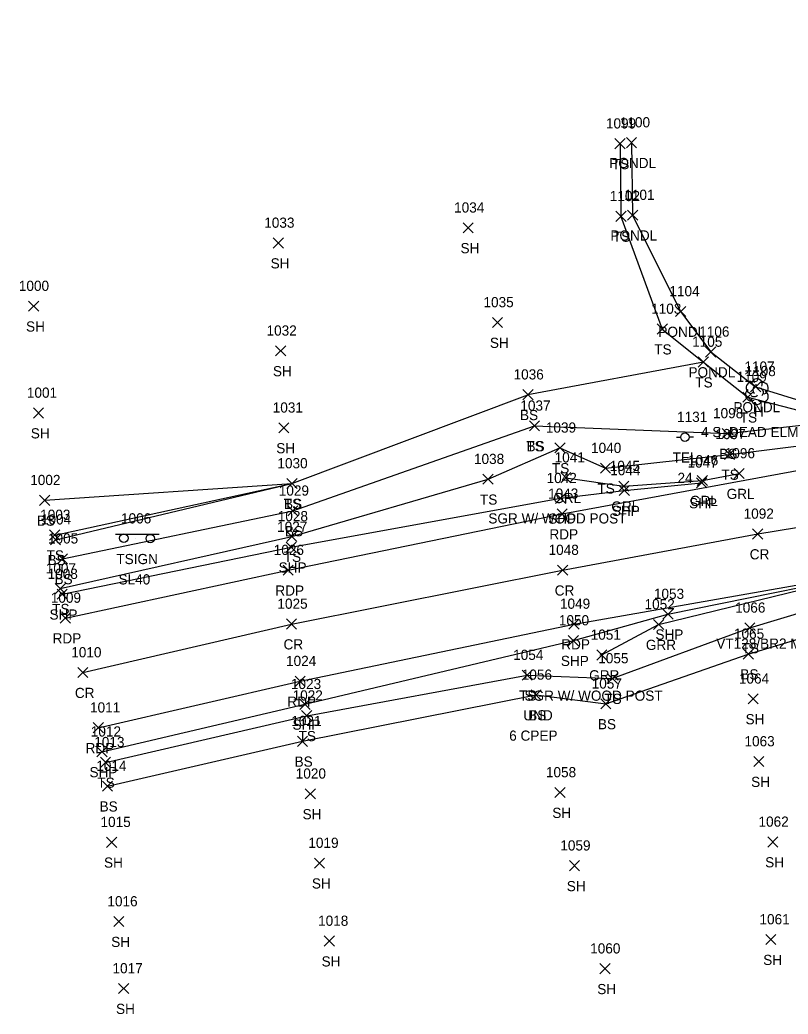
# Model space of a CAD drawing. Extents: x 1497084 to 1499861, y 734741 to 735567.
# Drawn here: x 1498155.1 to 1498306.3, y 735206.8 to 735402.3 of the extents above; entities that cross this region are included whole.
import ezdxf

# ---------------------------------------------------------------- set-up
doc = ezdxf.new("R2010")
doc.units = 0
for name, color, linetype in [('D_A', 7, 'Continuous'), ('D_C', 7, 'Continuous'), ('D_I', 7, 'Continuous'), ('D_TIC', 7, 'Continuous'), ('L_A', 7, 'Continuous'), ('L_C', 7, 'Continuous'), ('L_I', 7, 'Continuous'), ('L_TIC', 7, 'Continuous'), ('LAWE', 7, 'Continuous'), ('LELB', 7, 'Continuous'), ('LTD', 7, 'Continuous'), ('P_A', 7, 'Continuous'), ('P_I', 7, 'Continuous'), ('P_TIC', 7, 'Continuous'), ('PET', 7, 'Continuous'), ('PRC', 7, 'Continuous'), ('PSP', 7, 'Continuous'), ('R_A', 7, 'Continuous'), ('R_C', 7, 'Continuous'), ('R_I', 7, 'Continuous'), ('R_TIC', 7, 'Continuous'), ('RGR', 7, 'Continuous'), ('S_A', 7, 'Continuous'), ('S_C', 7, 'Continuous'), ('S_I', 7, 'Continuous'), ('SSGN', 7, 'Continuous'), ('U_A', 7, 'Continuous'), ('U_C', 7, 'Continuous'), ('U_I', 7, 'Continuous'), ('UP', 7, 'Continuous')]:
    doc.layers.add(name, color=color, linetype=linetype)

msp = doc.modelspace()

# ---------------------------------------------------------------- linework, layer by layer
at = {"layer": 'D_TIC'}
for points in [[(1498255.69, 735268.55), (1498257.69, 735270.55)], [(1498257.69, 735268.55), (1498255.69, 735270.55)]]:
    msp.add_lwpolyline(points, dxfattribs=at)
at = {"layer": 'L_TIC'}
for points in [[(1498272.21, 735376.95), (1498274.21, 735378.95)], [(1498274.21, 735376.95), (1498272.21, 735378.95)], [(1498274.46, 735377.17), (1498276.46, 735379.17)], [(1498276.46, 735377.17), (1498274.46, 735379.17)], [(1498272.39, 735362.67), (1498274.39, 735364.67)], [(1498274.39, 735362.67), (1498272.39, 735364.67)], [(1498274.69, 735362.91), (1498276.69, 735364.91)], [(1498276.69, 735362.91), (1498274.69, 735364.91)], [(1498242.32, 735360.42), (1498244.32, 735362.42)], [(1498244.32, 735360.42), (1498242.32, 735362.42)], [(1498204.95, 735357.43), (1498206.95, 735359.43)], [(1498206.95, 735357.43), (1498204.95, 735359.43)], [(1498156.81, 735345.01), (1498158.81, 735347.01)], [(1498158.81, 735345.01), (1498156.81, 735347.01)], [(1498284.13, 735343.96), (1498286.13, 735345.96)], [(1498286.13, 735343.96), (1498284.13, 735345.96)], [(1498248.1, 735341.8), (1498250.1, 735343.8)], [(1498250.1, 735341.8), (1498248.1, 735343.8)], [(1498280.53, 735340.51), (1498282.53, 735342.51)], [(1498282.53, 735340.51), (1498280.53, 735342.51)], [(1498205.4, 735336.22), (1498207.4, 735338.22)], [(1498207.4, 735336.22), (1498205.4, 735338.22)], [(1498290.05, 735336.01), (1498292.05, 735338.01)], [(1498292.05, 735336.01), (1498290.05, 735338.01)], [(1498288.61, 735334.02), (1498290.61, 735336.02)], [(1498290.61, 735334.02), (1498288.61, 735336.02)], [(1498298.89, 735329.14), (1498300.89, 735331.14)], [(1498300.89, 735329.14), (1498298.89, 735331.14)], [(1498254.08, 735327.59), (1498256.08, 735329.59)], [(1498256.08, 735327.59), (1498254.08, 735329.59)], [(1498297.36, 735327.12), (1498299.36, 735329.12)], [(1498299.36, 735327.12), (1498297.36, 735329.12)], [(1498157.74, 735324), (1498159.74, 735326)], [(1498159.74, 735324), (1498157.74, 735326)], [(1498206.05, 735321.08), (1498208.05, 735323.08)], [(1498208.05, 735321.08), (1498206.05, 735323.08)], [(1498255.36, 735321.46), (1498257.36, 735323.46)], [(1498257.36, 735321.46), (1498255.36, 735323.46)], [(1498255.36, 735321.46), (1498257.36, 735323.46)], [(1498257.36, 735321.46), (1498255.36, 735323.46)], [(1498293.28, 735319.97), (1498295.28, 735321.97)], [(1498295.28, 735319.97), (1498293.28, 735321.97)], [(1498260.39, 735317.14), (1498262.39, 735319.14)], [(1498262.39, 735317.14), (1498260.39, 735319.14)], [(1498293.75, 735315.86), (1498295.75, 735317.86)], [(1498295.75, 735315.86), (1498293.75, 735317.86)], [(1498269.35, 735313.14), (1498271.35, 735315.14)], [(1498271.35, 735313.14), (1498269.35, 735315.14)], [(1498207.63, 735310.12), (1498209.63, 735312.12)], [(1498209.63, 735310.12), (1498207.63, 735312.12)], [(1498207.63, 735310.12), (1498209.63, 735312.12)], [(1498209.63, 735310.12), (1498207.63, 735312.12)], [(1498207.63, 735310.12), (1498209.63, 735312.12)], [(1498209.63, 735310.12), (1498207.63, 735312.12)], [(1498246.23, 735310.97), (1498248.23, 735312.97)], [(1498248.23, 735310.97), (1498246.23, 735312.97)], [(1498158.97, 735306.83), (1498160.97, 735308.83)], [(1498160.97, 735306.83), (1498158.97, 735308.83)], [(1498207.82, 735304.75), (1498209.82, 735306.75)], [(1498209.82, 735304.75), (1498207.82, 735306.75)], [(1498160.93, 735299.99), (1498162.93, 735301.99)], [(1498162.93, 735299.99), (1498160.93, 735301.99)], [(1498207.61, 735299.72), (1498209.61, 735301.72)], [(1498209.61, 735299.72), (1498207.61, 735301.72)], [(1498161.08, 735299.08), (1498163.08, 735301.08)], [(1498163.08, 735299.08), (1498161.08, 735301.08)], [(1498162.46, 735295.33), (1498164.46, 735297.33)], [(1498164.46, 735295.33), (1498162.46, 735297.33)], [(1498162.03, 735289.46), (1498164.03, 735291.46)], [(1498164.03, 735289.46), (1498162.03, 735291.46)], [(1498297.74, 735281.74), (1498299.74, 735283.74)], [(1498299.74, 735281.74), (1498297.74, 735283.74)], [(1498297.45, 735276.6), (1498299.45, 735278.6)], [(1498299.45, 735276.6), (1498297.45, 735278.6)], [(1498253.94, 735272.44), (1498255.94, 735274.44)], [(1498255.94, 735272.44), (1498253.94, 735274.44)], [(1498270.69, 735271.78), (1498272.69, 735273.78)], [(1498272.69, 735271.78), (1498270.69, 735273.78)], [(1498255.69, 735268.55), (1498257.69, 735270.55)], [(1498257.69, 735268.55), (1498255.69, 735270.55)], [(1498269.41, 735266.8), (1498271.41, 735268.8)], [(1498271.41, 735266.8), (1498269.41, 735268.8)], [(1498298.42, 735267.78), (1498300.42, 735269.78)], [(1498300.42, 735267.78), (1498298.42, 735269.78)], [(1498210.53, 735264.46), (1498212.53, 735266.46)], [(1498212.53, 735264.46), (1498210.53, 735266.46)], [(1498209.71, 735259.44), (1498211.71, 735261.44)], [(1498211.71, 735259.44), (1498209.71, 735261.44)], [(1498170.92, 735255.29), (1498172.92, 735257.29)], [(1498172.92, 735255.29), (1498170.92, 735257.29)], [(1498299.52, 735255.45), (1498301.52, 735257.45)], [(1498301.52, 735255.45), (1498299.52, 735257.45)], [(1498171.32, 735250.62), (1498173.32, 735252.62)], [(1498173.32, 735250.62), (1498171.32, 735252.62)], [(1498211.24, 735249.1), (1498213.24, 735251.1)], [(1498213.24, 735249.1), (1498211.24, 735251.1)], [(1498260.4, 735249.36), (1498262.4, 735251.36)], [(1498262.4, 735249.36), (1498260.4, 735251.36)], [(1498172.15, 735239.58), (1498174.15, 735241.58)], [(1498174.15, 735239.58), (1498172.15, 735241.58)], [(1498302.28, 735239.64), (1498304.28, 735241.64)], [(1498304.28, 735239.64), (1498302.28, 735241.64)], [(1498213.07, 735235.48), (1498215.07, 735237.48)], [(1498215.07, 735235.48), (1498213.07, 735237.48)], [(1498263.23, 735234.96), (1498265.23, 735236.96)], [(1498265.23, 735234.96), (1498263.23, 735236.96)], [(1498173.57, 735223.98), (1498175.57, 735225.98)], [(1498175.57, 735223.98), (1498173.57, 735225.98)], [(1498214.98, 735220.15), (1498216.98, 735222.15)], [(1498216.98, 735220.15), (1498214.98, 735222.15)], [(1498301.9, 735220.44), (1498303.9, 735222.44)], [(1498303.9, 735220.44), (1498301.9, 735222.44)], [(1498269.24, 735214.71), (1498271.24, 735216.71)], [(1498271.24, 735214.71), (1498269.24, 735216.71)], [(1498174.52, 735210.81), (1498176.52, 735212.81)], [(1498176.52, 735210.81), (1498174.52, 735212.81)]]:
    msp.add_lwpolyline(points, dxfattribs=at)
at = {"layer": 'LAWE'}
msp.add_lwpolyline([(1498275.46, 735378.17), (1498275.69, 735363.91), (1498285.13, 735344.96), (1498291.05, 735337.01), (1498299.89, 735330.14), (1498310.47, 735326.85), (1498319.02, 735327.27), (1498323.8, 735327.85), (1498325.54, 735326.28), (1498335.98, 735328.26), (1498338.67, 735333.84), (1498347.71, 735340.62), (1498357.75, 735341.88), (1498365.93, 735349.29), (1498368.84, 735359.24), (1498365.54, 735374.35), (1498361.93, 735386.41), (1498357.1, 735395.06), (1498356, 735402.31)], dxfattribs=at)
at = {"layer": 'LELB'}
for points in [[(1498273.21, 735377.95), (1498273.39, 735363.67), (1498281.53, 735341.51), (1498289.61, 735335.02), (1498298.36, 735328.12), (1498310.25, 735325.02), (1498319.03, 735326.22), (1498322.65, 735326.67), (1498324.11, 735325.25)], [(1498289.61, 735335.02), (1498255.08, 735328.59)], [(1498162.08, 735300.08), (1498208.63, 735311.12), (1498255.08, 735328.59)], [(1498163.46, 735296.33), (1498208.82, 735305.75), (1498256.36, 735322.46), (1498294.28, 735320.97), (1498308.34, 735322.56), (1498324.11, 735325.25), (1498324.6, 735325.29), (1498324.94, 735324.79), (1498325.7, 735320.69), (1498326.21, 735318.71)], [(1498163.03, 735290.46), (1498208.61, 735300.72), (1498247.23, 735311.97), (1498261.39, 735318.14), (1498270.35, 735314.14), (1498294.75, 735316.86), (1498325.7, 735320.69)], [(1498159.97, 735307.83), (1498208.63, 735311.12)], [(1498161.93, 735300.99), (1498208.63, 735311.12)], [(1498171.92, 735256.29), (1498211.53, 735265.46), (1498254.94, 735273.44), (1498271.69, 735272.78), (1498298.74, 735282.74), (1498328.59, 735291.76)], [(1498172.32, 735251.62), (1498210.71, 735260.44), (1498256.69, 735269.55), (1498270.41, 735267.8), (1498298.45, 735277.6), (1498319.31, 735283.84), (1498321.64, 735282.68)]]:
    msp.add_lwpolyline(points, dxfattribs=at)
at = {"layer": 'LTD'}
msp.add_line((1498300.11, 735329.25), (1498300.11, 735329.25), dxfattribs=at)
msp.add_line((1498300.11, 735329.25), (1498300.11, 735329.25), dxfattribs=at)
msp.add_arc((1498300.16, 735330.69), 1.05, 335.5272, 180.9563, dxfattribs=at)
for centre, major_axis, ratio, start_param, end_param in [((1498299.32, 735329.92), (1.21, -0.51), 0.895232, 1.570796, 4.712389), ((1498301.15, 735329.84), (-1.14, -0.48), 0.949671, 1.570796, 4.712389), ((1498299.03, 735328.54), (0.58, -1.04), 0.959034, 3.141593, 6.283185), ((1498299.9, 735329.71), (-0.208, -0.792), 0.645439, 3.141593, 6.283185), ((1498300.61, 735329.09), (-0.5, 0.667), 0.989748, 3.141593, 6.283185), ((1498301.11, 735328.42), (-1.09, 0.79), 0.841452, 1.570796, 4.712389), ((1498300.11, 735327.75), (0.26, 1.06), 0.942809, 1.570796, 4.712389), ((1498299.65, 735328.5), (-0.625, -0.083), 0.423636, 0, 3.141593)]:
    msp.add_ellipse(centre, major_axis=major_axis, ratio=ratio, start_param=start_param, end_param=end_param, dxfattribs=at)
at = {"layer": 'P_TIC'}
for points in [[(1498288.26, 735310.26), (1498290.26, 735312.26)], [(1498290.26, 735310.26), (1498288.26, 735312.26)], [(1498273.05, 735308.76), (1498275.05, 735310.76)], [(1498275.05, 735308.76), (1498273.05, 735310.76)], [(1498260.52, 735307.22), (1498262.52, 735309.22)], [(1498262.52, 735307.22), (1498260.52, 735309.22)], [(1498260.82, 735304.15), (1498262.82, 735306.15)], [(1498262.82, 735304.15), (1498260.82, 735306.15)], [(1498299.3, 735300.21), (1498301.3, 735302.21)], [(1498301.3, 735300.21), (1498299.3, 735302.21)], [(1498207.48, 735297.62), (1498209.48, 735299.62)], [(1498209.48, 735297.62), (1498207.48, 735299.62)], [(1498206.88, 735293.08), (1498208.88, 735295.08)], [(1498208.88, 735293.08), (1498206.88, 735295.08)], [(1498260.91, 735293.09), (1498262.91, 735295.09)], [(1498262.91, 735293.09), (1498260.91, 735295.09)], [(1498162.39, 735288.37), (1498164.39, 735290.37)], [(1498164.39, 735288.37), (1498162.39, 735290.37)], [(1498281.64, 735284.44), (1498283.64, 735286.44)], [(1498283.64, 735284.44), (1498281.64, 735286.44)], [(1498163.03, 735283.68), (1498165.03, 735285.68)], [(1498165.03, 735283.68), (1498163.03, 735285.68)], [(1498207.54, 735282.5), (1498209.54, 735284.5)], [(1498209.54, 735282.5), (1498207.54, 735284.5)], [(1498263.16, 735282.5), (1498265.16, 735284.5)], [(1498265.16, 735282.5), (1498263.16, 735284.5)], [(1498263.03, 735279.24), (1498265.03, 735281.24)], [(1498265.03, 735279.24), (1498263.03, 735281.24)], [(1498166.48, 735272.95), (1498168.48, 735274.95)], [(1498168.48, 735272.95), (1498166.48, 735274.95)], [(1498209.24, 735271.24), (1498211.24, 735273.24)], [(1498211.24, 735271.24), (1498209.24, 735273.24)], [(1498210.2, 735266.71), (1498212.2, 735268.71)], [(1498212.2, 735266.71), (1498210.2, 735268.71)], [(1498169.52, 735262.1), (1498171.52, 735264.1)], [(1498171.52, 735262.1), (1498169.52, 735264.1)], [(1498170.24, 735257.37), (1498172.24, 735259.37)], [(1498172.24, 735257.37), (1498170.24, 735259.37)]]:
    msp.add_lwpolyline(points, dxfattribs=at)
at = {"layer": 'PET'}
for points in [[(1498164.03, 735284.68), (1498207.88, 735294.08), (1498261.82, 735305.15), (1498326.23, 735317.05)], [(1498170.52, 735263.1), (1498210.24, 735272.24), (1498264.16, 735283.5), (1498329.95, 735295.03), (1498327.97, 735305.73), (1498326.23, 735317.05)]]:
    msp.add_lwpolyline(points, dxfattribs=at)
at = {"layer": 'PRC'}
msp.add_lwpolyline([(1498167.48, 735273.95), (1498208.54, 735283.5), (1498261.91, 735294.09), (1498300.3, 735301.21), (1498327.97, 735305.73)], dxfattribs=at)
at = {"layer": 'PSP'}
for points in [[(1498163.39, 735289.37), (1498208.48, 735298.62), (1498261.52, 735308.22), (1498274.05, 735309.76), (1498289.26, 735311.26)], [(1498171.24, 735258.37), (1498211.2, 735267.71), (1498264.03, 735280.24), (1498282.64, 735285.44), (1498329.95, 735295.03)]]:
    msp.add_lwpolyline(points, dxfattribs=at)
at = {"layer": 'R_TIC'}
for points in [[(1498295.64, 735312.09), (1498297.64, 735314.09)], [(1498297.64, 735312.09), (1498295.64, 735314.09)], [(1498261.53, 735311.27), (1498263.53, 735313.27)], [(1498263.53, 735311.27), (1498261.53, 735313.27)], [(1498272.96, 735309.6), (1498274.96, 735311.6)], [(1498274.96, 735309.6), (1498272.96, 735311.6)], [(1498288.42, 735310.71), (1498290.42, 735312.71)], [(1498290.42, 735310.71), (1498288.42, 735312.71)], [(1498279.81, 735282.4), (1498281.81, 735284.4)], [(1498281.81, 735282.4), (1498279.81, 735284.4)], [(1498268.64, 735276.41), (1498270.64, 735278.41)], [(1498270.64, 735276.41), (1498268.64, 735278.41)]]:
    msp.add_lwpolyline(points, dxfattribs=at)
at = {"layer": 'RGR'}
for points in [[(1498262.53, 735312.27), (1498273.96, 735310.6), (1498289.42, 735311.71), (1498296.64, 735313.09)], [(1498269.64, 735277.41), (1498280.81, 735283.4), (1498308.97, 735290.32), (1498329.84, 735294.05)]]:
    msp.add_lwpolyline(points, dxfattribs=at)
at = {"layer": 'SSGN'}
for p, q in [((1498173.88, 735301.2), (1498182.47, 735301.2)), ((1498177.9, 735300.3), (1498177.9, 735300.3))]:
    msp.add_line(p, q, dxfattribs=at)
for centre in [(1498175.54, 735300.37), (1498180.75, 735300.3)]:
    msp.add_circle(centre, 0.833, dxfattribs=at)
at = {"layer": 'UP'}
for p, q in [((1498284.33, 735320.24), (1498285.15, 735320.24)), ((1498285.99, 735320.24), (1498285.99, 735320.24)), ((1498287.65, 735320.24), (1498286.82, 735320.24)), ((1498286.82, 735320.24), (1498286.82, 735320.24)), ((1498287.65, 735320.24), (1498287.65, 735320.24))]:
    msp.add_line(p, q, dxfattribs=at)
msp.add_circle((1498285.99, 735320.24), 0.833, dxfattribs=at)

# ---------------------------------------------------------------- texts
at = {"layer": 'D_A'}
msp.add_text('UND', height=2, dxfattribs=at).set_placement((1498254.17, 735264.55))
at = {"layer": 'D_C'}
msp.add_text('6 CPEP', height=2, dxfattribs=at).set_placement((1498251.39, 735260.55))
at = {"layer": 'D_I'}
msp.add_text('1056', height=2, dxfattribs=at).set_placement((1498253.87, 735272.55))
at = {"layer": 'L_A'}
for s, p in [('PONDL', (1498271.09, 735373.17)), ('TS', (1498271.62, 735372.95)), ('PONDL', (1498271.31, 735358.91)), ('TS', (1498271.8, 735358.67)), ('SH', (1498241.81, 735356.42)), ('SH', (1498204.44, 735353.43)), ('SH', (1498156.3, 735341.01)), ('PONDL', (1498280.75, 735339.96)), ('SH', (1498247.59, 735337.8)), ('TS', (1498279.94, 735336.51)), ('SH', (1498204.89, 735332.22)), ('PONDL', (1498286.68, 735332.01)), ('TS', (1498288.02, 735330.02)), ('PONDL', (1498295.52, 735325.14)), ('BS', (1498253.52, 735323.59)), ('TS', (1498296.77, 735323.12)), ('H', (1498299.54, 735324.25)), ('SH', (1498157.23, 735320)), ('TS', (1498254.77, 735317.46)), ('BS', (1498254.8, 735317.46)), ('SH', (1498205.54, 735317.08)), ('BS', (1498292.72, 735315.97)), ('TS', (1498259.8, 735313.14)), ('TS', (1498293.16, 735311.86)), ('TS', (1498268.76, 735309.14)), ('TS', (1498207.03, 735306.12)), ('BS', (1498207.07, 735306.12)), ('BS', (1498207.07, 735306.12)), ('TS', (1498245.64, 735306.97)), ('BS', (1498158.42, 735302.83)), ('BS', (1498207.26, 735300.75)), ('TS', (1498160.34, 735295.99)), ('TS', (1498207.02, 735295.72)), ('BS', (1498160.52, 735295.08)), ('BS', (1498161.9, 735291.33)), ('TS', (1498161.44, 735285.46)), ('TS', (1498297.15, 735277.74)), ('BS', (1498296.89, 735272.6)), ('TS', (1498253.35, 735268.44)), ('TS', (1498270.1, 735267.78)), ('BS', (1498255.13, 735264.55)), ('BS', (1498268.85, 735262.8)), ('SH', (1498297.91, 735263.78)), ('TS', (1498209.94, 735260.46)), ('BS', (1498209.15, 735255.44)), ('TS', (1498170.33, 735251.29)), ('SH', (1498299.01, 735251.45)), ('BS', (1498170.77, 735246.62)), ('SH', (1498210.73, 735245.1)), ('SH', (1498259.88, 735245.36)), ('SH', (1498171.64, 735235.58)), ('SH', (1498301.77, 735235.64)), ('SH', (1498212.56, 735231.48)), ('SH', (1498262.72, 735230.96)), ('SH', (1498173.06, 735219.98)), ('SH', (1498214.47, 735216.15)), ('SH', (1498301.39, 735216.44)), ('SH', (1498268.73, 735210.71)), ('SH', (1498174.01, 735206.81))]:
    msp.add_text(s, height=2, dxfattribs=at).set_placement(p)
at = {"layer": 'L_C'}
msp.add_text('4 S. DEAD ELM', height=2, dxfattribs=at).set_placement((1498289.15, 735320.25))
at = {"layer": 'L_I'}
for s, p in [('1099', (1498270.43, 735380.95)), ('1100', (1498273.17, 735381.17)), ('1102', (1498271.19, 735366.67)), ('1101', (1498274.05, 735366.91)), ('1034', (1498240.55, 735364.42)), ('1033', (1498203.18, 735361.43)), ('1000', (1498154.88, 735349.01)), ('1104', (1498282.92, 735347.96)), ('1035', (1498246.33, 735345.8)), ('1103', (1498279.33, 735344.51)), ('1032', (1498203.63, 735340.22)), ('1106', (1498288.79, 735340.01)), ('1105', (1498287.4, 735338.02)), ('1107', (1498297.69, 735333.14)), ('1036', (1498252.25, 735331.59)), ('1109', (1498296.15, 735331.12)), ('1108', (1498297.91, 735332.25)), ('1001', (1498156.46, 735328)), ('1031', (1498204.85, 735325.08)), ('1037', (1498253.59, 735325.46)), ('1037', (1498253.59, 735325.46)), ('1098', (1498291.51, 735323.97)), ('1039', (1498258.61, 735321.14)), ('1097', (1498291.98, 735319.86)), ('1040', (1498267.5, 735317.14)), ('1030', (1498205.77, 735314.12)), ('1030', (1498205.77, 735314.12)), ('1030', (1498205.77, 735314.12)), ('1038', (1498244.46, 735314.97)), ('1002', (1498157.12, 735310.83)), ('1029', (1498206.04, 735308.75)), ('1003', (1498159.08, 735303.99)), ('1028', (1498205.84, 735303.72)), ('1004', (1498159.23, 735303.08)), ('1005', (1498160.61, 735299.33)), ('1007', (1498160.18, 735293.46)), ('1066', (1498295.87, 735285.74)), ('1065', (1498295.63, 735280.6)), ('1054', (1498252.17, 735276.44)), ('1055', (1498268.92, 735275.78)), ('1056', (1498253.87, 735272.55)), ('1057', (1498267.63, 735270.8)), ('1064', (1498296.6, 735271.78)), ('1022', (1498208.76, 735268.46)), ('1021', (1498208.51, 735263.44)), ('1013', (1498169.72, 735259.29)), ('1063', (1498297.7, 735259.45)), ('1014', (1498170.12, 735254.62)), ('1020', (1498209.38, 735253.1)), ('1058', (1498258.62, 735253.36)), ('1015', (1498170.95, 735243.58)), ('1062', (1498300.46, 735243.64)), ('1019', (1498211.86, 735239.48)), ('1059', (1498261.45, 735238.96)), ('1016', (1498172.31, 735227.98)), ('1018', (1498213.78, 735224.15)), ('1061', (1498300.65, 735224.44)), ('1060', (1498267.33, 735218.71)), ('1017', (1498173.31, 735214.81))]:
    msp.add_text(s, height=2, dxfattribs=at).set_placement(p)
at = {"layer": 'P_A'}
for s, p in [('SHP', (1498286.8, 735306.26)), ('SHP', (1498271.59, 735304.76)), ('SHP', (1498259.06, 735303.22)), ('RDP', (1498259.31, 735300.15)), ('CR', (1498298.73, 735296.21)), ('SHP', (1498206.01, 735293.62)), ('RDP', (1498205.37, 735289.08)), ('CR', (1498260.35, 735289.09)), ('SHP', (1498160.92, 735284.37)), ('SHP', (1498280.17, 735280.44)), ('RDP', (1498161.52, 735279.68)), ('CR', (1498206.98, 735278.5)), ('RDP', (1498261.64, 735278.5)), ('SHP', (1498261.56, 735275.24)), ('CR', (1498165.91, 735268.95)), ('RDP', (1498207.73, 735267.24)), ('SHP', (1498208.74, 735262.71)), ('RDP', (1498168.01, 735258.1)), ('SHP', (1498168.78, 735253.37))]:
    msp.add_text(s, height=2, dxfattribs=at).set_placement(p)
at = {"layer": 'P_I'}
for s, p in [('1047', (1498286.49, 735314.26)), ('1044', (1498271.28, 735312.76)), ('1042', (1498258.75, 735311.22)), ('1043', (1498259.05, 735308.15)), ('1092', (1498297.53, 735304.21)), ('1027', (1498205.71, 735301.62)), ('1026', (1498205.05, 735297.08)), ('1048', (1498259.14, 735297.09)), ('1008', (1498160.54, 735292.37)), ('1053', (1498279.87, 735288.44)), ('1009', (1498161.17, 735287.68)), ('1025', (1498205.77, 735286.5)), ('1049', (1498261.38, 735286.5)), ('1050', (1498261.17, 735283.24)), ('1010', (1498165.19, 735276.95)), ('1024', (1498207.47, 735275.24)), ('1023', (1498208.43, 735270.71)), ('1011', (1498168.89, 735266.1)), ('1012', (1498169.04, 735261.37))]:
    msp.add_text(s, height=2, dxfattribs=at).set_placement(p)
at = {"layer": 'R_A'}
for s, p in [('GRL', (1498294.19, 735308.09)), ('GRL', (1498260.07, 735307.27)), ('GRL', (1498271.5, 735305.6)), ('GRL', (1498286.97, 735306.71)), ('GRR', (1498278.29, 735278.4)), ('GRR', (1498267.13, 735272.41))]:
    msp.add_text(s, height=2, dxfattribs=at).set_placement(p)
at = {"layer": 'R_C'}
for p in [(1498247.29, 735303.27), (1498254.4, 735268.41)]:
    msp.add_text('SGR W/ WOOD POST', height=2, dxfattribs=at).set_placement(p)
at = {"layer": 'R_I'}
for s, p in [('1041', (1498260.33, 735315.27)), ('1096', (1498293.82, 735316.09)), ('1045', (1498271.18, 735313.6)), ('1046', (1498286.6, 735314.71)), ('1052', (1498278.03, 735286.4)), ('1051', (1498267.43, 735280.41))]:
    msp.add_text(s, height=2, dxfattribs=at).set_placement(p)
at = {"layer": 'S_A'}
msp.add_text('TSIGN', height=2, dxfattribs=at).set_placement((1498174.07, 735295.28))
at = {"layer": 'S_C'}
for s, p in [('SL40', (1498174.5, 735291.28)), ('VT128/BR2 MM 1280/0406/0080', (1498292.15, 735278.65))]:
    msp.add_text(s, height=2, dxfattribs=at).set_placement(p)
at = {"layer": 'S_I'}
msp.add_text('1006', height=2, dxfattribs=at).set_placement((1498174.99, 735303.28))
at = {"layer": 'U_A'}
msp.add_text('TEL', height=2, dxfattribs=at).set_placement((1498283.55, 735315.24))
at = {"layer": 'U_C'}
msp.add_text('24', height=2, dxfattribs=at).set_placement((1498284.52, 735311.24))
at = {"layer": 'U_I'}
msp.add_text('1131', height=2, dxfattribs=at).set_placement((1498284.43, 735323.24))

doc.saveas('drawing.dxf')
